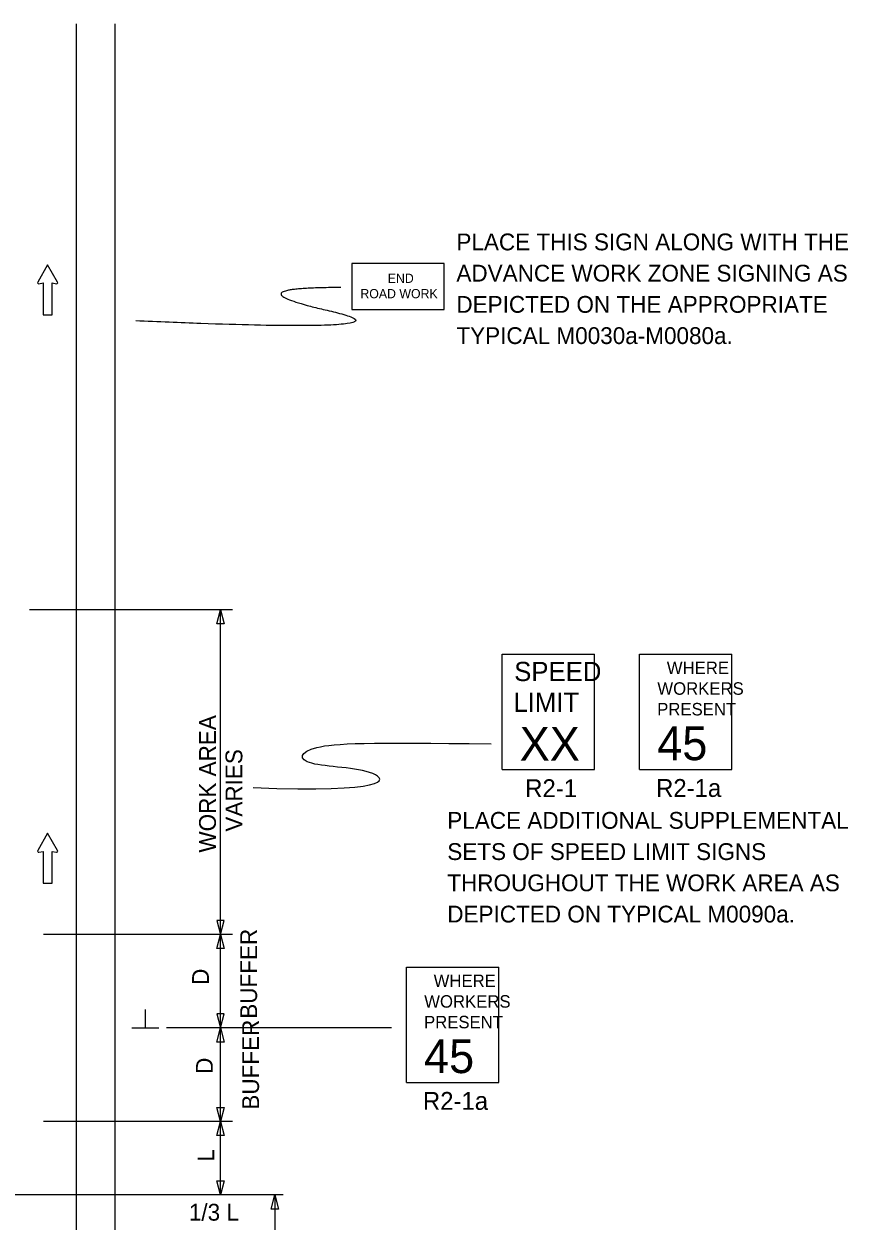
# Model space of a CAD drawing. Extents: x 16729 to 18475, y 5706 to 6927.
# Drawn here: x 17061.7 to 17404.5, y 6361.4 to 6859.6 of the extents above; entities that cross this region are included whole.
import ezdxf

# ---------------------------------------------------------------- set-up
doc = ezdxf.new("R2010")
doc.units = 0
for name, color, linetype in [('MT_SCRATCH_LEVEL_E', 7, 'Continuous'), ('PAVT_EDGE_EX', 7, 'Continuous'), ('TRAFFIC_SIGNS_PR', 7, 'Continuous'), ('TYPICAL_TEXT_DIMEN_PR', 7, 'Continuous')]:
    doc.layers.add(name, color=color, linetype=linetype)

msp = doc.modelspace()

# ---------------------------------------------------------------- linework, layer by layer
at = {"layer": 'MT_SCRATCH_LEVEL_E'}
for p, q in [((17071.54, 6759.44), (17067.43, 6752.2)), ((17071.54, 6759.44), (17067.43, 6752.2)), ((17075.69, 6752.2), (17071.54, 6759.44)), ((17075.69, 6752.2), (17071.54, 6759.44)), ((17067.91, 6751.51), (17069.69, 6751.83)), ((17067.91, 6751.51), (17069.69, 6751.83)), ((17069.69, 6751.83), (17069.69, 6738.57)), ((17069.69, 6751.83), (17069.69, 6738.57)), ((17073.43, 6738.57), (17073.43, 6751.83)), ((17073.43, 6751.83), (17075.21, 6751.51)), ((17073.43, 6738.57), (17073.43, 6751.83)), ((17073.43, 6751.83), (17075.21, 6751.51)), ((17069.69, 6738.57), (17073.43, 6738.57)), ((17069.69, 6738.57), (17073.43, 6738.57)), ((17071.54, 6522.88), (17067.43, 6515.64)), ((17071.54, 6522.88), (17067.43, 6515.64)), ((17075.69, 6515.64), (17071.54, 6522.88)), ((17075.69, 6515.64), (17071.54, 6522.88)), ((17067.91, 6514.95), (17069.69, 6515.27)), ((17067.91, 6514.95), (17069.69, 6515.27)), ((17069.69, 6515.27), (17069.69, 6502.01)), ((17069.69, 6515.27), (17069.69, 6502.01)), ((17073.43, 6502.01), (17073.43, 6515.27)), ((17073.43, 6515.27), (17075.21, 6514.95)), ((17073.43, 6502.01), (17073.43, 6515.27)), ((17073.43, 6515.27), (17075.21, 6514.95)), ((17069.69, 6502.01), (17073.43, 6502.01)), ((17069.69, 6502.01), (17073.43, 6502.01))]:
    msp.add_line(p, q, dxfattribs=at)
for centre, start, end in [((17067.84, 6751.97), 150.4248, 279.9638), ((17067.84, 6751.97), 150.4248, 279.9638), ((17075.28, 6751.97), 260.0362, 29.7731), ((17075.28, 6751.97), 260.0362, 29.7731), ((17067.84, 6515.41), 150.4248, 279.9638), ((17067.84, 6515.41), 150.4248, 279.9638), ((17075.28, 6515.41), 260.0362, 29.7731), ((17075.28, 6515.41), 260.0362, 29.7731)]:
    msp.add_arc(centre, 0.463, start, end, dxfattribs=at)
at = {"layer": 'PAVT_EDGE_EX'}
for p, q in [((17083.43, 6859.63), (17083.43, 6100.51)), ((17099.43, 6859.63), (17099.43, 6100.51))]:
    msp.add_line(p, q, dxfattribs=at)
at = {"layer": 'TRAFFIC_SIGNS_PR'}
for p, q in [((17260.57, 6597.27), (17298.97, 6597.27)), ((17260.57, 6549.27), (17260.57, 6597.27)), ((17298.97, 6549.27), (17298.97, 6597.27)), ((17317.77, 6597.36), (17356.17, 6597.36)), ((17317.77, 6549.36), (17317.77, 6597.36)), ((17356.17, 6549.36), (17356.17, 6597.36)), ((17260.57, 6549.27), (17298.97, 6549.27)), ((17317.77, 6549.36), (17356.17, 6549.36)), ((17220.78, 6467.13), (17259.18, 6467.13)), ((17220.78, 6419.13), (17220.78, 6467.13)), ((17259.18, 6419.13), (17259.18, 6467.13)), ((17220.78, 6419.13), (17259.18, 6419.13))]:
    msp.add_line(p, q, dxfattribs=at)
msp.add_lwpolyline([(17198.01, 6740.73), (17236.41, 6740.73), (17236.41, 6759.93), (17198.01, 6759.93)], close=True, dxfattribs=at)
msp.add_open_spline([(17193.47, 6749.91), (17146.24, 6749.91), (17231.26, 6730.56), (17108.16, 6736.05)], degree=2, dxfattribs=at)
at = {"layer": 'TYPICAL_TEXT_DIMEN_PR'}
for p, q in [((17148.43, 6615.84), (17063.94, 6615.84)), ((17141.86, 6609.98), (17143.43, 6615.84)), ((17143.43, 6480.67), (17143.43, 6615.84)), ((17143.43, 6615.84), (17145, 6609.98)), ((17143.43, 6609.98), (17141.86, 6609.98)), ((17145, 6609.98), (17143.43, 6609.98)), ((17143.43, 6486.53), (17141.86, 6486.53)), ((17141.86, 6486.53), (17143.43, 6480.67)), ((17143.43, 6480.67), (17145, 6486.53)), ((17145, 6486.53), (17143.43, 6486.53)), ((17148.43, 6480.67), (17069.76, 6480.67)), ((17141.86, 6474.81), (17143.43, 6480.67)), ((17143.43, 6441.75), (17143.43, 6480.67)), ((17143.43, 6480.67), (17145, 6474.81)), ((17143.43, 6474.81), (17141.86, 6474.81)), ((17145, 6474.81), (17143.43, 6474.81)), ((17112.19, 6441.72), (17112.19, 6449.5)), ((17143.43, 6447.61), (17141.86, 6447.61)), ((17141.86, 6447.61), (17143.43, 6441.75)), ((17143.43, 6441.75), (17145, 6447.61)), ((17145, 6447.61), (17143.43, 6447.61)), ((17117.82, 6441.72), (17106.57, 6441.72)), ((17214.54, 6441.75), (17120.96, 6441.75)), ((17141.86, 6435.88), (17143.43, 6441.75)), ((17143.43, 6402.82), (17143.43, 6441.75)), ((17143.43, 6441.75), (17145, 6435.88)), ((17143.43, 6435.88), (17141.86, 6435.88)), ((17145, 6435.88), (17143.43, 6435.88)), ((17143.43, 6402.82), (17141.86, 6408.69)), ((17141.86, 6408.69), (17143.43, 6408.69)), ((17143.43, 6408.69), (17145, 6408.69)), ((17145, 6408.69), (17143.43, 6402.82)), ((17148.43, 6402.82), (17069.76, 6402.82)), ((17141.86, 6396.96), (17143.43, 6402.82)), ((17143.43, 6402.82), (17145, 6396.96)), ((17143.43, 6372.25), (17143.43, 6402.82)), ((17143.43, 6396.96), (17141.86, 6396.96)), ((17145, 6396.96), (17143.43, 6396.96)), ((17143.43, 6372.25), (17141.86, 6378.11)), ((17141.86, 6378.11), (17143.43, 6378.11)), ((17143.43, 6378.11), (17145, 6378.11)), ((17145, 6378.11), (17143.43, 6372.25)), ((17169.54, 6372.25), (17042.79, 6372.25)), ((17164.48, 6366.39), (17166.05, 6372.25)), ((17166.05, 6372.25), (17167.62, 6366.39)), ((17166.05, 6372.25), (17166.05, 6333.33)), ((17166.05, 6366.39), (17164.48, 6366.39)), ((17167.62, 6366.39), (17166.05, 6366.39))]:
    msp.add_line(p, q, dxfattribs=at)
msp.add_open_spline([(17156.98, 6541.81), (17213.46, 6539.64), (17213.05, 6550.3), (17174.6, 6550.3), (17177.08, 6559.92), (17204.61, 6560.7), (17256.07, 6559.97)], degree=3, dxfattribs=at)

# ---------------------------------------------------------------- texts
at = {"layer": 'TRAFFIC_SIGNS_PR'}
for s, height, p in [('PLACE THIS SIGN ALONG WITH THE', 7, (17241.56, 6765.41)), ('ADVANCE WORK ZONE SIGNING AS', 7, (17241.56, 6752.41)), ('END', 3.831, (17213.01, 6751.86)), ('ROAD WORK', 3.831, (17201.62, 6745.47)), ('DEPICTED ON THE APPROPRIATE', 7, (17241.56, 6739.41)), ('TYPICAL M0030a-M0080a.', 7, (17241.56, 6726.41)), ('SPEED', 8, (17265.61, 6586.13)), ('WHERE', 5.2, (17329.08, 6589.04)), ('WORKERS', 5.2, (17325.15, 6580.44)), ('LIMIT', 8, (17265.28, 6573.33)), ('PRESENT', 5.2, (17325.09, 6571.84)), ('XX', 14.031, (17267.88, 6553.03)), ('45', 14.031, (17325.08, 6553.21)), ('R2-1', 7.44, (17270.18, 6537.83)), ('R2-1a', 7.44, (17324.62, 6537.92)), ('PLACE ADDITIONAL SUPPLEMENTAL', 7, (17237.77, 6524.66)), ('SETS OF SPEED LIMIT SIGNS', 7, (17237.77, 6511.66)), ('THROUGHOUT THE WORK AREA AS', 7, (17237.77, 6498.66)), ('DEPICTED ON TYPICAL M0090a.', 7, (17237.77, 6485.66)), ('WHERE', 5.2, (17232.1, 6458.81)), ('WORKERS', 5.2, (17228.17, 6450.21)), ('PRESENT', 5.2, (17228.1, 6441.61)), ('45', 14.031, (17228.09, 6422.98)), ('R2-1a', 7.44, (17227.64, 6407.69))]:
    msp.add_text(s, height=height, dxfattribs=at).set_placement(p)
at = {"layer": 'TYPICAL_TEXT_DIMEN_PR'}
for s, p in [('WORK AREA', (17141.53, 6514.75)), ('VARIES', (17152.53, 6523.47)), ('BUFFER', (17158.66, 6445.6)), ('D', (17138.63, 6459.69)), ('BUFFER', (17159.46, 6407.76)), ('D', (17140.24, 6422.65)), ('L', (17140.88, 6386.12))]:
    msp.add_text(s, height=7, rotation=90, dxfattribs=at).set_placement(p)
msp.add_text('1/3 L', height=7, dxfattribs=at).set_placement((17130.28, 6361.57))

doc.saveas('drawing.dxf')
